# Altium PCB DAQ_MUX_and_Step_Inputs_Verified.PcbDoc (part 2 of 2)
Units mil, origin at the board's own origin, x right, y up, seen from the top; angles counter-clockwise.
Board outline 3200 x 1700 mil, 4 copper layers (Top Layer, InternalPlane1, InternalPlane2, Bottom Layer), stack 61.7 mil thick; 78 components, 60 nets, 284 pads, 100 vias.
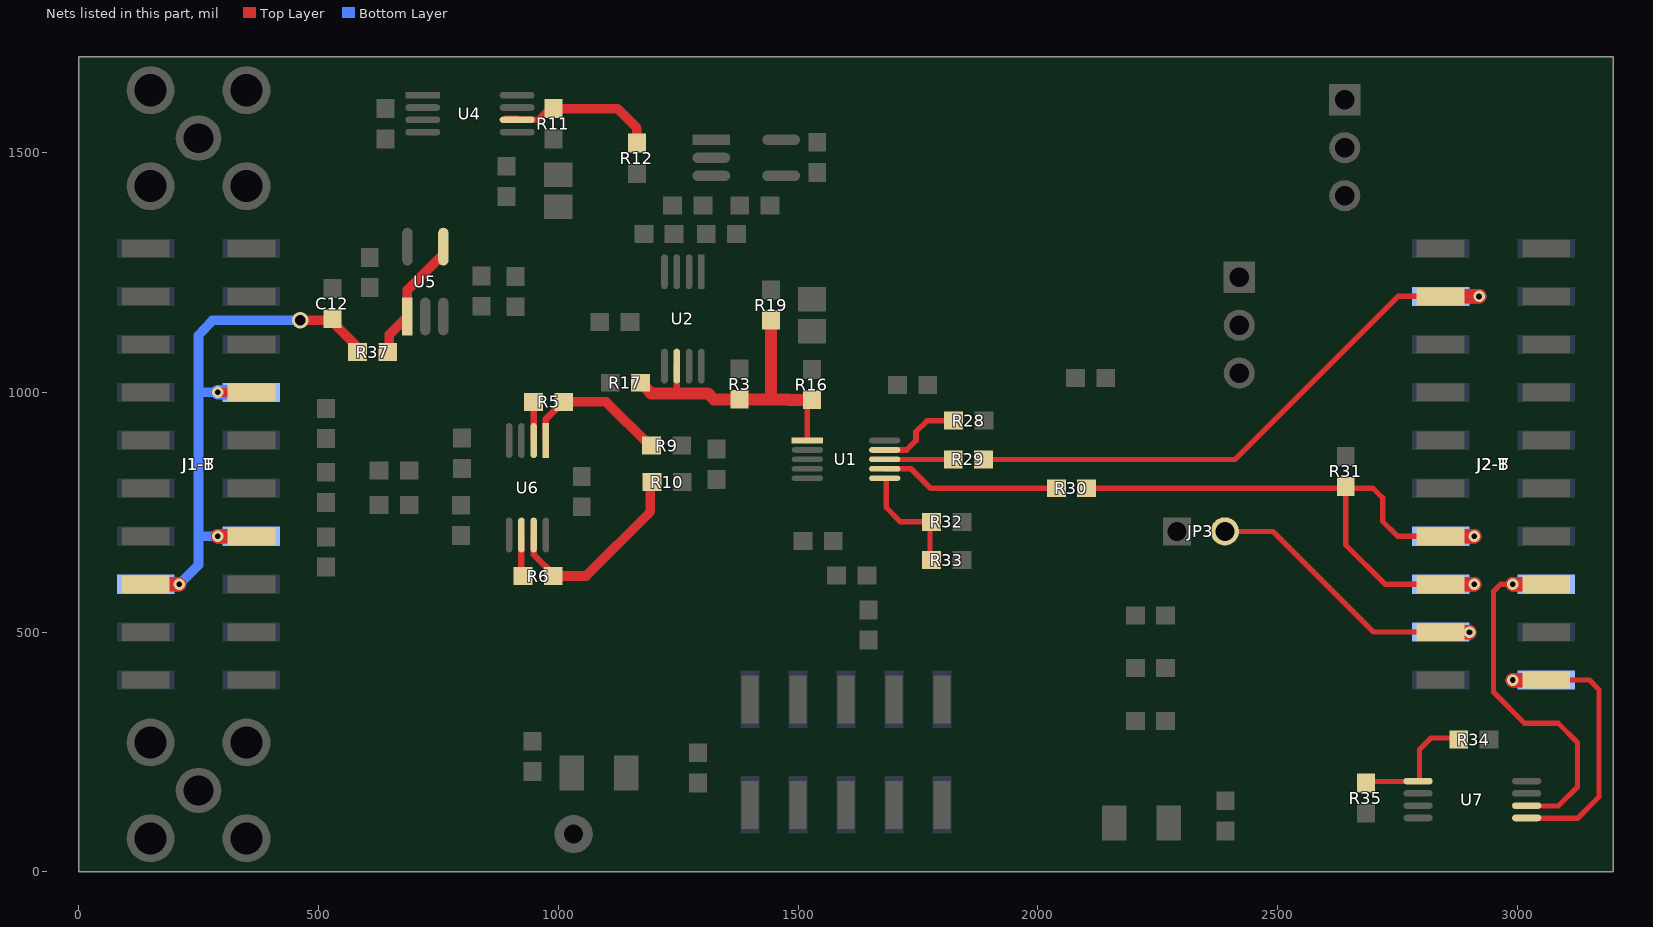
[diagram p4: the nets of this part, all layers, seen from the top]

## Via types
v1: diameter 24, hole 12, Top Layer to Bottom Layer, tented both sides, 50 vias
v2: diameter 34/34 (per signal layer), hole 22, Top Layer to Bottom Layer, 47 vias
v3: diameter 34, hole 22, Top Layer to Bottom Layer, 3 vias

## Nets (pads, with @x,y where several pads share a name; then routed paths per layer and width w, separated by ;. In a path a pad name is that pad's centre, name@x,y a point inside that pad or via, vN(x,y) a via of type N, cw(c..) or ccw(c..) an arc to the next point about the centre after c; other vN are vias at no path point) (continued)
NetR3_2: R3.2 R16.1 R17.2 R19.2 U1.1 U2.6 | length 675.6
  Top Layer w11.81: U1.1@1519.29,899.62 1519.29,974.8 R16.1@1529,984.5
  Top Layer w13.78: 1247.2,1007.2 U2.6@1247.2,1054.57
  Top Layer w25: R17.2@1171.5,1020 1193.71,997.78 1312.22,997.78 1324.5,985.5 R3.2@1378,985.5 1449,985.5 ; R19.2@1444,1150.5 1444,990.5 1449,985.5 ; R16.1@1529,984.5 1480,984.5 1479,985.5 1449,985.5
NetR5_1: R5.1 U6.2 | length 80.7
  Top Layer w13.78: R5.1@948.5,980 948.8,979.71 U6.2@948.8,899.43
NetR5_2: R5.2 R9.1 U6.1 | length 314
  Top Layer w13.78: U6.1@974.39,899.43 974.39,944.39 1010,980 R5.2@1011.5,980
  Top Layer w20: R5.2@1011.5,980 1100,980 R9.1@1191,889
NetR6_1: R6.1 U6.6 | length 85.7
  Top Layer w13.78: R6.1@923,617 923.2,617.2 U6.6@923.2,702.57
NetR6_2: R6.2 R10.1 U6.7 | length 420.4
  Top Layer w13.78: U6.7@948.8,702.57 948.8,661.2 R6.2@993,617
  Top Layer w20: R6.2@993,617 1058,617 1192,751 R10.1@1192,813
NetR11_1: R11.1 R12.1 U4.6 | length 331.8
  Top Layer w13.78: U4.6@914.43,1568.2 957.72,1568.2 R11.1@984.52,1595
  Top Layer w15: U4.6@891.6,1569.8 U4.6@914.43,1569.8
  Top Layer w20: R11.1@984.52,1595 R11.1@990,1595 ; R11.1@990,1591.5 1123.5,1591.5 1164,1551 R12.1@1164,1519.5
NetR28_1: R28.1 U1.9 | length 176.4
  Top Layer w11: 1768.55,940.55 1820.55,940.55 R28.1@1821,941
  Top Layer w11.81: U1.9@1680.71,879.94 1726.39,879.94 1746,899.55 1746,918 1768.55,940.55
NetR29_1: R29.1 U1.8 | length 136.2
  Top Layer w11: U1.8@1684,859.85 1820,859.85 R29.1@1820,860
NetR30_1: R30.1 U1.7 | length 371.1
  Top Layer w11.81: U1.7@1680.71,840.57 1735.59,840.57 1776.15,800 R30.1@2035,800
NetR32_1: R32.1 R33.1 U1.6 | length 243.9
  Top Layer w11: U1.6@1684,820.45 1684,760 1714,730 1775,730 R33.1@1775,650
NetR34_1: R34.1 R35.1 U7.1 | length 267.8
  Top Layer w11: R35.1@2684,189 2684.4,188.6 2795.9,188.6 2795.9,255 2820,279.1 2870.9,279.1 R34.1@2874,276
NetR37_1: R37.1 U5.1 U5.4 | length 247.9
  Top Layer w20: R37.1@648,1084 648,1120.57 U5.1@685.6,1158.17 ; U5.1@685.6,1159.6 685.6,1213.6 757.5,1285.5 U5.4@760,1285.5
SCL: J2-B.16 J2-T.16 U7.6 | length 832.1
  Top Layer w11: v1@2990.1,600 v1(2990,600.1) 2965.1,600.1 2950,585 2950,375 3015,310 3085,310 3125,270 3125,177.4 3085,137.4 U7.6@3016.9,137.4
  Top Layer w30: v1@2990.1,600 J2-T.16@3060,600
  Bottom Layer w30: v1(2990,600.1) 2990.1,600 J2-B.16@3060,600
SCLK: J2-B.3 J2-T.3 R29.2 | length 1250.9
  Top Layer w11: R29.2@1890,860 2411,860 2751.1,1200.1 J2-T.3@2840,1200.1
  Top Layer w30: J2-T.3@2840,1200.1 2840.1,1200 v1(2920,1200)
  Bottom Layer w30: J2-B.3@2840,1200 v1(2920,1200)
SDA: J2-B.20 J2-T.20 U7.5 | length 653.3
  Top Layer w11: U7.5@3016.9,111.8 3125,111.8 3170,156.8 3170,380 3149.9,400.1 J2-T.20@3060,400.1
  Top Layer w30: v1(2990,400) J2-T.20@3060,400
  Bottom Layer w30: v1(2990,400) J2-B.20@3060,400
SDO: J2-B.13 J2-B.15 J2-T.13 J2-T.15 R30.2 R31.2 | length 1434.9
  Top Layer w11: R30.2@2105,800 R31.2@2642,800 ; J2-T.15@2840,600.1 2724,600.1 2642,682.1 R31.2@2642,800 ; J2-T.13@2840,700.1 2750,700.1 2719,731.1 2719,780 2699,800 R31.2@2642,800
  Top Layer w30: J2-T.15@2840,600.1 2840.1,600 v1(2910,600) ; J2-T.13@2840,700 v1(2910,700)
  Bottom Layer w30: J2-B.15@2840,600 v1(2910,600) ; J2-B.13@2840,700 v1(2910,700)
TOUT: J2-B.17 J2-T.17 JP3.2 | length 656.9
  Top Layer w11: JP3.2@2390,710 2490.1,710 2700,500.1 J2-T.17@2840,500.1
  Top Layer w30: J2-T.17@2840,500 v1(2900,500)
  Bottom Layer w30: J2-B.17@2840,500 v1(2900,500)
VCM: C12.2 J1-B.8 J1-B.14 J1-B.15 J1-T.8 J1-T.14 J1-T.15 R37.2 | length 1400.4
  Top Layer w20: v1(290,1000) J1-T.8@360,1000 ; v2(462,1150) 529,1150 538,1141 538,1138 R37.2@578,1098
  Top Layer w30: J1-T.15@140,600 v1(210,600) ; v1(290,700) J1-T.14@360,700
  Bottom Layer w20: v1(210,600) 250,640 250,700.1 ; v1@290,700.1 250,700.1 ; v1@290,1000.1 250,1000.1 ; v2(462,1150) 279,1150 250,1119 250,1000.1 ; 250,700.1 250,1000.1
  Bottom Layer w30: J1-B.15@140,600 v1(210,600) ; v1(290,700) J1-B.14@360,700 ; v1@290,1000.1 290.1,1000 J1-B.8@360,1000
pads on no net: SH-JP1.0 SH-JP2.0 SH-JP3.0 U2.1 U2.5 U2.8 U4.1 U4.3 U4.7 U4.8

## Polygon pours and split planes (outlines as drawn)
AGND on InternalPlane1 (split plane): 3179.9,20.1 20.1,20.1 20.1,1679.9 3179.9,1679.9
DVDD on InternalPlane2 (split plane): 3173.95,26.05 1646.05,26.05 1646.05,1673.95 3173.95,1673.95
AVDD on InternalPlane2 (split plane): 1533.95,26.05 26.05,26.05 26.05,1673.95 1533.95,1673.95

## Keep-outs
Keep-Out Layer:
  the board outline again, w10
  text ".Layer_Name" at 527,-858.49 h60

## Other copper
Top Layer:
  region net AGND: 1492,820 1455,783 1455,734 1550,734 1550,820 1492,820
  text ".Layer_Name" at 527,-858.49 h60
Bottom Layer:
  text ".Layer_Name" at 527,-858.49 h60
InternalPlane1 (plane layer: these items are gaps in the copper):
  region: 3200,0 0,0 0,1700 3200,1700 hole: 3190,1690 10,1690 10,10 3190,10 3189.98,255 3189.98,255 3190.03,475 3190,475
  lines w10: 3189.98,255 3189.98,255 ; 3189.98,255 3190,10 10,10 10,1690 3190,1690 3190,475 3190.03,475 3189.98,255
InternalPlane2 (plane layer: these items are gaps in the copper):
  region: 3200,0 0,0 0,1700 3200,1700 hole: 3180,1680 1640,1680 1640,20 3180,20 hole: 1540,1680 20,1680 20,20 1540,20
  lines w12: 20,20 1540,20 1540,1680 20,1680 20,20 ; 1640,20 1640,1680 3180,1680 3180,20 1640,20

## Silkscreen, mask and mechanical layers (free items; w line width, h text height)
Top Overlay:
  region: 1570,945 1630,945 1630,925 1570,925 1570,945
  region: 2855,235 2955,235 2955,215 2855,215 2855,235
  lines w12: 3144,54.16 3160,50.16 3160,25 3161,25 3161,38.03 3175,41.03 3175,61 3176,61 3176,42 3161,42 3161,91 3160,91 3160,55 3145,55 3145,79 3144,79 3144,54.16
  text "1" at 2551.43,1636 h30
  text "Rev A" at 2979.87,1621 h40
  text "Texas" at 1830.35,1615.01 h50
  text "CS0" at 2461.72,1581.5 h30
  text "Instruments" at 1962.78,1520.01 h50
  text "(c) 2013" at 1847.23,1422.15 h30
  text "FSX" at 2460.65,1416.5 h30
  text "(MMB0)" at 2424.02,1348.65 h30
  text "TI Design" at 1800.64,1328.39 h40
  text "1" at 24.43,1284 h30
  text "1" at 2335.43,1283 h30
  text "1" at 2733.43,1253 h30
  text "1MSPS 18bit" at 1751.13,1250.05 h40
  text "4Wire" at 2238.23,1218.79 h30
  text "70mW" at 1840.35,1166.5 h35
  text "3Wire" at 2233.23,1015.79 h30
  text "4Wire" at 2070,700 h30
  text "+5VD" at 2027.01,521 h30
  text "+3.3VD" at 1983.94,411 h30
  text "+1.8VD" at 1991.3,301 h30
  text "1" at 1395.43,11 h30
  text ".Layer_Name" at 527,-858.49 h60
Bottom Overlay:
  lines w12: 60,340 430,340 430,1360 60,1360 60,340 ; 1339,60 1859,60 1859,431 1339,431 1339,60 ; 2760,340 3130,340 3130,1360 2760,1360 2760,340
  text ".PRJ_Rev" at 793.49,1531 h60
  text ".PRJ_BasePN" at 1213.49,1531 h60
  text "1" at 35,1285 h30
  text "1" at 2745,1251 h30
  text "1" at 1401,10 h30
  text ".Layer_Name" at 527,-858.49 h60
Top Paste:
  text ".Layer_Name" at 527,-858.49 h60
Bottom Paste:
  text ".Layer_Name" at 527,-858.49 h60
Top Solder:
  text ".Layer_Name" at 527,-858.49 h60
  text ".Layer_Name" at 527,-858.49 h60
Bottom Solder:
  text ".Layer_Name" at 527,-858.49 h60
Drill Guide:
  text ".Layer_Name" at 527,-858.49 h60
M1 Board Outline:
  the board outline again, w10
M2 Board Dimensions:
  rectangle: 124.5,-410.5 499.5,-285.5
  rectangle: -0.5,-285.5 124.5,-160.5
  lines w7: -0.5,-285.5 999.5,-285.5 ; 124.5,-410.5 124.5,-160.5 ; 249.5,-410.5 249.5,-160.5 ; 499.5,-410.5 499.5,-160.5 ; 749.5,-410.5 749.5,-160.5 ; -0.5,-410.5 -0.5,-160.5 999.5,-160.5 999.5,-410.5 -0.5,-410.5
  lines w10: -0.5,-475.5 -0.5,-455.5 ; 59.5,-485.5 -0.5,-465.5 ; 59.5,-445.5 -0.5,-465.5 ; 223.58,-465.5 -0.5,-465.5 ; 775.42,-465.5 999.5,-465.5 ; 939.5,-485.5 999.5,-465.5 ; 939.5,-445.5 999.5,-465.5 ; 999.5,-475.5 999.5,-455.5
  text "1000 (mil)" at 233.58,-501.49 h60
  text ".Layer_Name" at 577,-858.49 h60
M3 3D STEP Top:
  text ".Layer_Name" at 577,-858.49 h60
M4 3D STEP Bottom:
  text ".Layer_Name" at 577,-858.49 h60
M5 Assembly Top:
  lines w10: -496.51,-1129 4403.49,-1129 ; -496.51,-929 4403.49,-929 ; 2203.49,-929 2203.49,-729 ; -496.51,-1329 -496.51,-729 4403.49,-729 4403.49,-1329 -496.51,-1329
  text "ASSEMBLY, TOP," at 11103.49,-279 h150
  text "COMPONENTS MARKED 'DNI' SHOULD NOT BE POPULATED, AND MAY NOT BE IN BILL OF MATERIALS" at 1353.49,-379 h60
  text "ASSEMBLY VARIANT:" at 1353,-484 h60
  text ".VariantName" at 2389,-484 h60
  text "PCB VIEWED FROM TOP SIDE" at -246.51,-679 h60
  text ".Layer_Name" at 577,-858.49 h60
  text "LAYER NAME =" at -246.51,-879 h60
  text "ARTWORK #    =" at 2253.49,-879 h60
  text ".PRJ_BasePN" at 3253.49,-879 h60
  text ".PCB_Rev" at 3753.49,-879 h60
  text "PLOT NAME =" at -246.51,-1079 h60
  text ".plot_File_Name" at 553.49,-1079 h60
  text "1" at 13688,-1240.65 h80
  text "GENERATED    :" at -246.51,-1279 h60
  text ".Print_Date" at 622.99,-1279 h60
  text ".Print_Time" at 1303.49,-1279 h60
  text "2" at 13981,-1295.65 h80
M6 Assembly Bottom:
  lines w10: -496.51,-1129 4403.49,-1129 ; -496.51,-929 4403.49,-929 ; 2203.49,-929 2203.49,-729 ; -496.51,-1329 4403.49,-1329 4403.49,-729 -496.51,-729 -496.51,-1329
  text "ASSEMBLY, BOTTOM," at 11103.49,-279 h150
  text "COMPONENTS MARKED 'DNI' SHOULD NOT BE POPULATED, AND MAY NOT BE IN BILL OF MATERIALS" at 1353.49,-379 h60
  text "ASSEMBLY VARIANT:" at 1353.49,-479 h60
  text ".VariantName" at 2389,-484 h60
  text "PCB VIEWED FROM TOP SIDE" at -246.51,-679 h60
  text "LAYER NAME =" at -246.51,-879 h60
  text "ARTWORK #    =" at 2253.49,-879 h60
  text ".PRJ_BasePN" at 3253.49,-879 h60
  text ".PCB_Rev" at 3753.49,-879 h60
  text "PLOT NAME =" at -246.51,-1079 h60
  text ".plot_File_Name" at 553.49,-1079 h60
  text "2" at 13688,-1240.65 h80
  text "GENERATED    :" at -246.51,-1279 h60
  text ".Print_Date" at 622.99,-1279 h60
  text ".Print_Time" at 1303.49,-1279 h60
  text "2" at 13981,-1295.65 h80
M9 Title Sheet:
  drawing of 222 lines, arcs and shapes, not listed
  text "1" at 534.83,7841 h70
  text "2" at 3030.49,7841 h70
  text "3" at 5519.84,7841 h70
  text "4" at 8026.5,7841 h70
  text "5" at 10525.49,7841 h70
  text "6" at 13030.49,7841 h70
  text "SYM" at 11283.72,7663.3 h90
  text "REVISIONS" at 12450,7650 h90
  text "A" at 11376.36,7379.35 h100
  text "06/07/2013" at 11681,7379.35 h100
  text "," at 12661,7379.35 h100
  text "B McKay" at 12931,7379.35 h100
  text "A" at -621.51,6698 h70
  text "A" at 14178.49,6698 h70
  text "B" at -621.51,4318 h70
  text "B" at 14178.49,4318 h70
  text "PROCESSES:" at 11044.01,2316.57 h76
  text "MATERIAL:" at 9485.96,2309.98 h76
  text "C" at -621.51,1943 h70
  text "C" at 14178.49,1943 h70
  text "NEXT ASSEMBLY" at 12888.64,1748 h76
  text "SURFACE" at 13508.83,1570.43 h59
  text "TOLERANCES UNLESS OTHERWISE SPECIFIED" at 9992.61,1514.88 h85
  text "ROUGHNESS" at 13452.84,1480.01 h59
  text "LINEAR" at 10271.94,1268.88 h80
  text "MISCELLANEOUS" at 11933.99,1268.88 h80
  text "MILLIMETERS" at 9700.02,1148.88 h50
  text "INCHES" at 10792.32,1148.88 h50
  text "o" at 12160.51,1114.27 h20
  text "ANGLES +/- 1" at 11560.29,1073.88 h50
  text ".XX  +/- .25" at 9581.29,1023.88 h50
  text ".XXX +/- .010" at 10646.52,1023.88 h50
  text "o" at 12735.51,989.27 h20
  text "o" at 13060.51,989.27 h20
  text "THIRD ANGLE" at 13407,963.81 h59
  text ".X   +/- .50" at 9581.31,948.88 h50
  text ".XX  +/- .020" at 10581.82,948.88 h50
  text "AXIS OF TAPPED HOLES 90  +/- 1" at 11560.29,948.88 h50
  text "PROJECTION" at 13439.75,866.11 h59
  text "REMOVE ALL BURRS & SHARP EDGES" at 11560.29,823.88 h50
  text "HOLES" at 10285.6,797.29 h80
  text "MILLIMETERS" at 9704.37,698.88 h50
  text "INCHES" at 10796.67,698.88 h50
  text ".XXX +/- .076" at 9581.28,573.88 h50
  text ".XXX +/- .003" at 10581.28,573.88 h50
  text ".XX  +/- .127" at 9581.29,498.88 h50
  text ".XX  +/- .005" at 10581.28,498.88 h50
  text "DATE" at 10486.45,291.8 h59
  text "CODE IDENTITY" at 13402.46,288.55 h51
  text "DRAFTSMAN:" at 9443.49,283.36 h59
  text "NUMBER" at 13550.1,215.25 h51
  text ".PRJ_Draftsman" at 9456,139.39 h60
  text ".PRJ_ReleaseDate" at 10368,136.54 h60
  text "SEMICONDUCTOR OPERATIONS" at 12100,120.04 h50
  text "01295" at 13465.68,85.84 h106
  text "TI" at 11050,50.04 h300
  text "DESIGNER:" at 9443.49,-9.86 h59
  text "DATE" at 10476.45,-11.42 h59
  text "TITLE:" at 11044.06,-89.16 h59
  text ".PRJ_Designer" at 9456,-135.61 h60
  text ".PRJ_ReleaseDate" at 10368,-143.46 h60
  text "CHECKER:" at 9443.49,-307.34 h59
  text "DATE" at 10471.45,-313.89 h59
  text "D" at -621.51,-427 h70
  text "D" at 14178.49,-427 h70
  text ".PRJ_Checker" at 9446,-430.61 h60
  text ".PRJ_ReleaseDate" at 10368,-433.46 h60
  text ".PRJ_Title1" at 11055.99,-540.61 h150
  text "DATE" at 10471.45,-567.36 h59
  text "ENGINEER:" at 9443.49,-570.81 h59
  text ".PRJ_Engr" at 9436,-700.61 h60
  text ".PRJ_ReleaseDate" at 10368,-703.46 h60
  text ".PRJ_Title2" at 11065.99,-765.61 h150
  text "Texas Instruments (TI) and/or its licensors do not warrant the accuracy or completeness of this specification" at 4456.49,-801.8 h45
  text "APPROVED:" at 9443.49,-834.28 h59
  text "DATE" at 10476.45,-835.84 h59
  text "or any information contained therein. TI and/or its licensors do not warrant that this design will meet" at 4411.51,-914.46 h45
  text ".PRJ_Release" at 9426,-970.61 h60
  text ".PRJ_ReleaseDate" at 10368,-973.46 h60
  text ".PRJ_Title3" at 11065.99,-990.61 h150
  text "the specifications, will be suitable for your application or fit for any particular purpose, or will operate in" at 4411.51,-1027.13 h45
  text "RELEASED:" at 9443.49,-1114.75 h59
  text "SHEET" at 13684.86,-1132.5 h51
  text "SCALE" at 11065.53,-1133.59 h51
  text "DATE" at 10476.45,-1136.31 h59
  text "an implementation. TI and/or its licensors do not warrant that the design is production worthy. You should" at 4411.51,-1139.79 h45
  text ".PRJ_Rev" at 13391,-1195.61 h100
  text "B" at 11472.79,-1218.96 h125
  text "B McKay" at 9446,-1250.61 h60
  text "completely validate and test your design implementation to confirm the system functionality for your application." at 4456.49,-1252.46 h45
  text ".PRJ_ReleaseDate" at 10368,-1253.46 h60
  text ".PRJ_BasePN" at 11919.5,-1265.61 h150
  text "N" at 11147.45,-1278.96 h100
  text "REV" at 13392.02,-1291.88 h51
  text "SIZE" at 11430.21,-1294.17 h51
  text "1" at 534.83,-1459 h70
  text "2" at 3030.49,-1459 h70
  text "3" at 5519.84,-1459 h70
  text "4" at 8026.5,-1459 h70
  text "5" at 10525.49,-1459 h70
  text "6" at 13030.49,-1459 h70
M10 Fab Notes:
  drawing of 203 lines, arcs and shapes, not listed
  text "NOTES:" at 11300,7100 h100
  text "1. MAXIMUM ALLOWABLE LINE REDUCTION TO BE" at 11330,6960 h60
  text "20% OR .002 WHICHEVER IS GREATER" at 11589.44,6834.91 h60
  text "HOLES TO BE .002 INCH" at 11613.17,6709.91 h60
  text "2. SELECTIVE GOLD PLATING OUTER LAYERS" at 11328,6580.85 h60
  text "(IF PRESENT) TO BE PLATED WITH" at 11500,6450 h60
  text "A) DUT PADS (HG-TOP) MIN 50 uIN Au" at 11593,6330.85 h60
  text "OVER 200 uIN Ni," at 11893,6230.85 h60
  text "KNOOP HARDNESS 130-200" at 11893,6130.85 h60
  text "B) ALL REMAINING PADS 5-15 uIN OVER" at 11600,6000 h60
  text "200 uIN Ni, KNOOP HARDNESS 130-200." at 11900,5900 h60
  text "DESIGN INFORMATION" at 7001.02,5750 h60
  text "(REFER ALSO ARRAY/PANEL PROFILING INFORMATION)" at 6639.46,5588.29 h60
  text "BOARD SIZE" at 5953.46,5584 h60
  text "3200MIL" at 6415.78,5456.18 h60
  text "X" at 6921.46,5456.18 h60
  text "1700MIL" at 7152.78,5456.18 h60
  text "Number of Layers :" at 6356.46,5259 h60
  text "4" at 7451.27,5249 h60
  text "MIN. TRACK WIDTH:" at 6356.46,5120 h60
  text "8" at 7452.7,5120 h60
  text "MIL" at 7607.46,5120 h60
  text "MIN. CLEARANCE:" at 6356.46,4988 h60
  text "8" at 7452.7,4988 h60
  text "MIL" at 7607.46,4988 h60
  text "MIN. VIA PAD SIZE:" at 6356.46,4856 h60
  text "40" at 7422.71,4856 h60
  text "MIL" at 7607.46,4856 h60
  text "0.05mm (2MIL)" at 7051.46,4714.29 h60
  text "MINIMUM ANNULAR RING" at 6027.23,4710 h60
  text "EXTERNAL" at 7759.46,4710 h60
  text "PER" at 6227.23,4592 h60
  text "IPC-D-275 CLASS 2 LEVEL C" at 6447.23,4592 h60
  text "MIL, HOLES" at 7935.46,4479.71 h60
  text "+/-" at 7543,4479 h60
  text "+/-" at 8397,4479 h60
  text "REGISTRATION TOLERANCES:" at 6027.23,4474 h60
  text "METAL" at 7227,4474 h60
  text "5" at 7803.2,4474 h60
  text "3" at 8636.2,4474 h60
  text "MIL" at 8752.46,4474 h60
  text "MATERIAL:" at 5952.46,4264.54 h60
  text "FR-4 High Tg" at 6938.9,4124.21 h60
  text "FR-4" at 6413.46,4115.64 h60
  text "OTHER" at 7861.46,4115.64 h60
  text "X" at 6220,4110 h60
  text "62 MIL (1.6mm) +/-10%" at 6693.56,3952.92 h60
  text "THICKNESS:" at 6027.23,3948.64 h60
  text "X" at 6565.4,3948.64 h60
  text "OTHER" at 7978.46,3948.64 h60
  text "TOLERANCE:" at 6027.23,3790.64 h60
  text "X" at 6866.53,3790.64 h60
  text "ANSI IPC-6012 TYPE 3 CLASS 2" at 7053.48,3790.64 h60
  text "OTHER +/-" at 7053.46,3634.64 h60
  text "BOW & TWIST:" at 6027.23,3477.64 h60
  text "X" at 6866.53,3477.64 h60
  text "ANSI IPC-6012 TYPE 3 CLASS 2" at 7053.48,3477.64 h60
  text "OTHER +/-" at 7053.46,3319.13 h60
  text "COPPER THICKNESS (FINISHED):" at 5952.46,3183.64 h60
  text "1.4MIL (1oz)" at 6832.46,3030.92 h60
  text "2MIL (1.4oz)" at 7599.46,3030.92 h60
  text "2.8MIL (2oz)" at 8326.46,3030.92 h60
  text "OUTER:" at 6309.46,3026.64 h60
  text "X" at 6704,3026 h60
  text "1.4MIL (1oz)" at 7182.46,2873.92 h60
  text "2.8MIL (2oz)" at 8026.46,2873.92 h60
  text "INNER SIGNAL:" at 6309.46,2869.64 h60
  text "X" at 7055.42,2869.64 h60
  text "DRILLING:" at 5952.46,2730.64 h60
  text "REFERENCE:" at 6027.23,2613.64 h60
  text "X" at 6675.46,2613.64 h60
  text "AS SHOWN" at 6862.46,2613.64 h60
  text "X" at 7576.46,2613.64 h60
  text "NC_DRILL FILES" at 7713.46,2613.64 h60
  text "PTH MIN COPPER THICKNESS:" at 6027.23,2455.64 h60
  text "X" at 7377.46,2455.64 h60
  text "1MIL" at 7514.46,2455.64 h60
  text "OTHER" at 8011.46,2455.64 h60
  text "BOARD FINISH:" at 5952.46,2296.64 h60
  text "SILKSCREEN:" at 6107.68,2178.64 h60
  text "X" at 7056.46,2178.64 h60
  text "TOP" at 7182.46,2178.64 h60
  text "X" at 7566.46,2178.64 h60
  text "BOTTOM" at 7693.46,2178.64 h60
  text "SILKSCREEN COLOR:" at 6107.68,2011.64 h60
  text "X" at 7055.42,2011.64 h60
  text "WHITE" at 7182.46,2011.64 h60
  text "OTHER" at 7693.46,2011.64 h60
  text "SOLDER RESIST COLOR:" at 6107.68,1841.64 h60
  text "X" at 6675.42,1682.44 h60
  text "GREEN" at 6802.46,1682.44 h60
  text "BLUE" at 7393.46,1682.44 h60
  text "OTHER" at 7931.46,1682.44 h60
  text "IMMERSION GOLD (ENIG)" at 7013.46,1493.92 h60
  text "SURFACE FINISH:" at 5952.46,1489.64 h60
  text "Pb-FREE HASL" at 8245.75,1489.64 h60
  text "X" at 8110,1480 h60
  text "OTHER" at 7013.46,1332.64 h60
  text "ARRAY/PANEL:" at 5952.46,1153.64 h60
  text "CUT AND TRIM PER MECH LAYER 1" at 7013.46,1149.35 h60
  text "X" at 6830,1140 h60
  text "N.C. ROUTE" at 7013.46,997.64 h60
  text "V. SCORE" at 7879.46,997.64 h60
  text "CERTIFICATION:" at 5952.46,860.64 h60
  text "MATERIALS AND WORKMANSHIP FOR ALL PCBS" at 6677.46,860.64 h60
  text "TO MEET OR EXCEED THE REQUIREMENTS OF:" at 6677.46,762.64 h60
  text "X" at 6303.96,626.13 h60
  text "ANSI IPC-A-600F CLASS ->" at 6442.96,626.13 h60
  text "X" at 8082.02,626.13 h60
  text "2" at 8200.96,626.14 h60
  text "1" at 7885.96,624.64 h60
  text "3" at 8554.96,624.64 h60
  text "X" at 6306.02,466.64 h60
  text "UL 94V-0" at 6442.96,466.64 h60
  text "X" at 7118.02,466.64 h60
  text "RoHS" at 7254.96,466.64 h60
  text "OTHER" at 7899.36,466.64 h60
  text "PER ORDER" at 8296.42,466.64 h60
  text "ADDITIONAL REQUIREMENTS:" at 5952.46,325.64 h60
  text "MICROSECTION:" at 6027.23,210.64 h60
  text "YES" at 6932.96,210.64 h60
  text "REQUIRED" at 7794.46,54.49 h60
  text "BARE BOARD ELEC. TEST:" at 6027.23,51.64 h60
  text "NONE" at 7332.96,51.64 h60
  text "X" at 7667.46,51.64 h60
  text "PER ORDER" at 8386.46,51.64 h60
  text "MANUFACTURER'S ID/LOGO:" at 6027.23,-105.36 h60
  text "RAIL" at 7492.96,-109.65 h60
  text "METAL" at 7984.77,-109.65 h60
  text "X" at 8353.49,-109.65 h60
  text "SILK" at 8496.46,-109.65 h60
  text ".Layer_Name" at 577,-858.49 h60
M11 Gerber Information:
  lines w10: -496.51,-1129 4403.49,-1129 ; -496.51,-929 4403.49,-929 ; 2203.49,-929 2203.49,-729 ; -496.51,-1329 4403.49,-1329 4403.49,-729 -496.51,-729 -496.51,-1329
  text "PCB VIEWED FROM TOP SIDE" at -246.51,-679 h60
  text "LAYER NAME =" at -246.51,-879 h60
  text "ARTWORK #    =" at 2253.49,-879 h60
  text ".PRJ_BasePN" at 3253.49,-879 h60
  text ".PCB_Rev" at 3753.49,-879 h60
  text "PLOT NAME =" at -246.51,-1079 h60
  text ".plot_File_Name" at 553.49,-1079 h60
  text "GENERATED    :" at -246.51,-1279 h60
  text ".Print_Date" at 622.99,-1279 h60
  text ".Print_Time" at 1303.49,-1279 h60
M12 Stackup:
  lines w10: -20,6917.5 5140,6917.5 ; -20,7095.6 5140,7095.6 ; -80,5417 ccw(c-23,5417) -23,5360 5143,5360 ccw(c5143,5417) 5200,5417 5200,7373 ccw(c5143,7373) 5143,7430 -23,7430 ccw(c-23,7373) -80,7373 -80,5417
  text "Layer Stack Up Detail for: 6572448.PcbDoc" at -20,7169.4 h123
  text "Layer" at -20,7029.1 h41
  text "Gerber" at 1087.69,7029.1 h41
  text "Copper" at 1647.08,7029.1 h41
  text "Dielectric" at 2273.43,7029.1 h41
  text "Dielectric" at 2928.46,7029.1 h41
  text "Dielectric" at 3751.24,7029.1 h41
  text "Dielectric" at 4406.27,7029.1 h41
  text "Name" at -20,6947.1 h41
  text "Document" at 1087.69,6947.1 h41
  text "Thickness" at 1647.08,6947.1 h41
  text "Height" at 2273.43,6947.1 h41
  text "Material" at 2928.46,6947.1 h41
  text "Constant" at 3751.24,6947.1 h41
  text "Type" at 4406.27,6947.1 h41
  text "Top Solder Mask" at -20,6799.79 h57
  text "(.GTS)" at 1087.69,6799.79 h57
  text "0.4mil" at 2273.43,6799.79 h57
  text "Solder Resist" at 2928.46,6799.79 h57
  text "3.50" at 3751.24,6799.79 h57
  text "Top Layer" at -20,6574.38 h57
  text "(.GTL)" at 1087.69,6574.38 h57
  text "1.4mil" at 1647.08,6574.38 h57
  text "12.6mil" at 2273.43,6461.67 h57
  text "FR-4" at 2928.46,6461.67 h57
  text "4.80" at 3751.24,6461.67 h57
  text "Core" at 4406.27,6461.67 h57
  text "InternalPlane1" at -20,6348.96 h57
  text "(.GP1)" at 1087.69,6348.96 h57
  text "1.4mil" at 1647.08,6348.96 h57
  text "30.9mil" at 2273.43,6236.25 h57
  text "FR-4" at 2928.46,6236.25 h57
  text "4.80" at 3751.24,6236.25 h57
  text "PrePreg" at 4406.27,6236.25 h57
  text "InternalPlane2" at -20,6123.54 h57
  text "(.GP2)" at 1087.69,6123.54 h57
  text "1.4mil" at 1647.08,6123.54 h57
  text "12.6mil" at 2273.43,6010.83 h57
  text "FR-4" at 2928.46,6010.83 h57
  text "4.80" at 3751.24,6010.83 h57
  text "Core" at 4406.27,6010.83 h57
  text "Bottom Layer" at -20,5898.13 h57
  text "(.GBL)" at 1087.69,5898.13 h57
  text "1.4mil" at 1647.08,5898.13 h57
  text "Bottom Solder Mask" at -20,5672.71 h57
  text "(.GBS)" at 1087.69,5672.71 h57
  text "0.4mil" at 2273.43,5672.71 h57
  text "Solder Resist" at 2928.46,5672.71 h57
  text "3.50" at 3751.24,5672.71 h57
  text ".Layer_Name" at 577,-858.49 h60
M13 Component Bodies Top:
  text ".Layer_Name" at 577,-858.49 h60
M14 Component Bodies Bottom:
  text ".Layer_Name" at 577,-858.49 h60
M15 Courtyards Top:
  text ".Layer_Name" at 577,-858.49 h60
M16 Courtyards Bottom:
  text ".Layer_Name" at 577,-858.49 h60
Drill Drawing:
  the board outline again, w1
  text ".legend" at 53.49,3821 h60
  text ".Layer_Name" at 527,-858.49 h60
M17 Fabrication:
  text "SEE NOTES" at 9631,1904.35 h120
  text "SEE NOTES" at 11231,1904.35 h120
  text "FABRICATION," at 11103.49,-279 h150
  text "1" at 13688,-1240.65 h80
  text "1" at 13981,-1295.65 h80

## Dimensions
0,0 to 3200,0 on M2 Board Dimensions
0,0 to 0,1700 on M2 Board Dimensions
